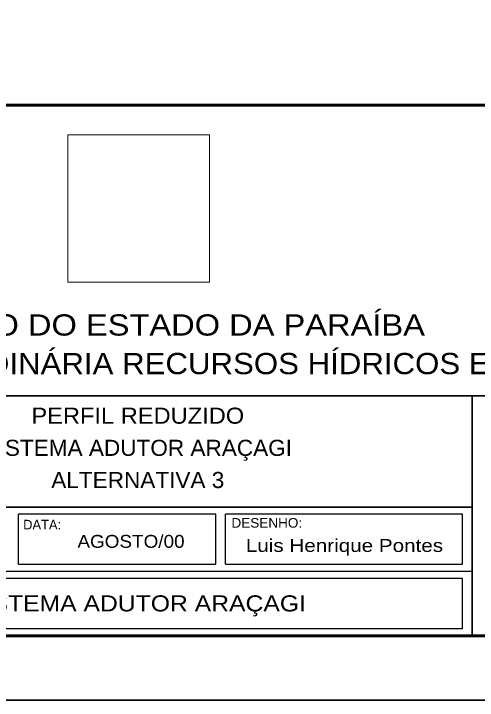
# Model space of a CAD drawing. Extents: x 0 to 1682, y 0 to 1188.
# Drawn here: x 1448 to 1592.2, y -0.1 to 213.3 of the extents above; entities that cross this region are included whole.
import ezdxf
from ezdxf.enums import TextEntityAlignment as Align

# ---------------------------------------------------------------- set-up
doc = ezdxf.new("R2010")
doc.units = 0
doc.header["$LTSCALE"] = 1.3
doc.layers.add('63', color=7, linetype='Continuous', lineweight=25)

msp = doc.modelspace()

# ---------------------------------------------------------------- linework, layer by layer
at = {"layer": '63', "lineweight": 60}
for p, q in [((1661.832, 184.881), (1311.832, 184.881)), ((1661.832, 19.881), (49.832, 19.881))]:
    msp.add_line(p, q, dxfattribs=at)
at = {"layer": '63', "lineweight": 35}
for p, q in [((1311.832, 94.561), (1661.832, 94.561)), ((1590.652, 19.921), (1590.652, 94.561)), ((1590.652, 59.921), (1383.012, 59.921))]:
    msp.add_line(p, q, dxfattribs=at)
at = {"layer": '63'}
for p, q in [((1510.892, 57.721), (1449.492, 57.721)), ((1449.492, 42.221), (1449.492, 57.721)), ((1449.492, 42.221), (1449.492, 57.721)), ((1510.892, 42.221), (1510.892, 57.721)), ((1587.652, 57.721), (1513.892, 57.721)), ((1513.892, 42.221), (1513.892, 57.721)), ((1587.652, 42.221), (1587.652, 57.721)), ((1449.492, 42.221), (1510.892, 42.221)), ((1513.892, 42.221), (1587.652, 42.221)), ((1590.652, 39.921), (1383.012, 39.921)), ((1587.652, 37.721), (1385.052, 37.721)), ((1587.652, 22.221), (1587.652, 37.721)), ((1385.052, 22.221), (1587.652, 22.221))]:
    msp.add_line(p, q, dxfattribs=at)
for points in [[(-0.168, -0.119), (1681.832, -0.119), (1681.832, 1187.881)], [(-0.168, -0.119), (1681.832, -0.119), (-0.168, -0.119)]]:
    msp.add_lwpolyline(points, dxfattribs=at)
at = {"layer": '63', "lineweight": 60}
msp.add_lwpolyline([(49.832, 1167.881), (1661.832, 1167.881), (1661.832, 19.881), (1311.832, 19.881)], dxfattribs=at)
at = {"layer": '63', "lineweight": 13}
msp.add_lwpolyline([(1464.792, 175.621), (1508.872, 175.621), (1508.872, 129.841), (1464.792, 129.841)], close=True, dxfattribs=at)

# ---------------------------------------------------------------- texts
at = {"layer": '63'}
for s, height, width, p in [('GOVERNO DO ESTADO DA PARAÍBA', 6.6, 1.15, (1486.822, 113.261)), ('SECRETARIA EXTRAORDINÁRIA RECURSOS HÍDRICOS E MINERAIS', 6.6, 1.1, (1486.832, 101.261)), ('PERFIL REDUZIDO', 5, 1.1, (1486.592, 85.861)), ('SISTEMA ADUTOR ARAÇAGI', 5, 1.05, (1486.592, 75.861)), ('ALTERNATIVA 3', 5, 1.05, (1486.592, 65.861)), ('AGOSTO/00', 4, 1.1, (1484.48, 47.281)), ('Luis Henrique Pontes', 4, 1.2, (1550.892, 46.001)), ('SISTEMA ADUTOR ARAÇAGI', 5, 1.15, (1486.362, 27.501))]:
    msp.add_text(s, height=height, dxfattribs=dict(at, width=width)).set_placement(p, align=Align.CENTER)
msp.add_text('DATA:', height=3, dxfattribs=at).set_placement((1456.832, 52.981), align=Align.CENTER)
at = {"layer": '63', "width": 1.05}
msp.add_text('DESENHO:', height=3, dxfattribs=at).set_placement((1515.732, 53.541))

doc.saveas('drawing.dxf')
